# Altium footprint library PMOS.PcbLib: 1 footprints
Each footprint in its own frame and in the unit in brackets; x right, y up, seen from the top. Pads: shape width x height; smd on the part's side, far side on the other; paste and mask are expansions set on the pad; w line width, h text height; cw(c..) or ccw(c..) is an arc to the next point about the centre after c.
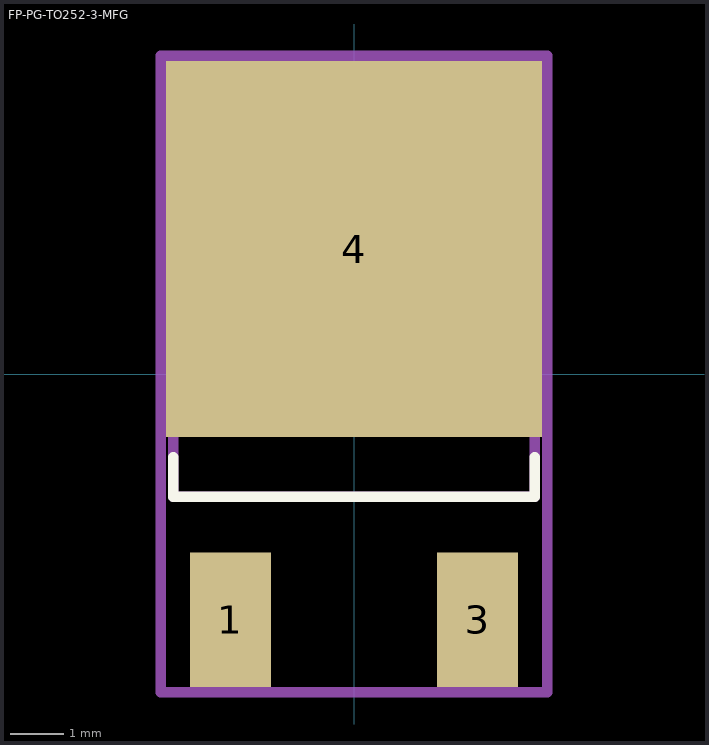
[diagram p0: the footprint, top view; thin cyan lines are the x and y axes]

## FP-PG-TO252-3-MFG [mm]
pads (3):
  rect 1.5x2.5 smd paste+0 mask+0: 1(-2.3,-4.575) 3(2.3,-4.575)
  rect 7x7 smd paste+0 mask+0: 4(0,2.325)
Top Overlay:
  lines w0.2: -3.365,-1.55 -3.365,-2.285 3.365,-2.285 3.365,-1.55
Top Assembly:
  lines w0.2: -3.6,-5.925 -3.6,5.925 3.6,5.925 3.6,-5.925 -3.6,-5.925
  text ".Designator" at 0,-0.001 h1
Top 3D Body:
  lines w0.2: -3.365,-2.285 -3.365,3.935 3.365,3.935 3.365,-2.285 -3.365,-2.285
Top Courtyard:
  lines w0.2: -3.6,-5.925 -3.6,5.925 3.6,5.925 3.6,-5.925 -3.6,-5.925
Top Component Center:
  lines w0.1: -0.5,0 0.5,0 ; 0,-0.5 0,0.5
3D body "Trans_Infineon_IRFR5410TRPBF_eec.STEP": height 0.25, standoff 0, extent -3.6,-5.925 3.6,5.925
